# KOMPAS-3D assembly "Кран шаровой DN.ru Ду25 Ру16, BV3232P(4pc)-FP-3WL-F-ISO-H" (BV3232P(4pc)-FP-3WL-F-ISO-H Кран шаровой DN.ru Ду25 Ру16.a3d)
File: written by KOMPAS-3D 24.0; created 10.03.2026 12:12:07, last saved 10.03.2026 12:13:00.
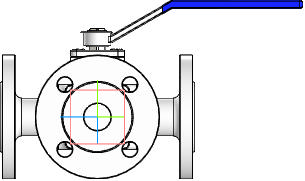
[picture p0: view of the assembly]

Document properties: Автор: R2D2; Полное имя файла: E:\Работа\Зайцев\BV3232P(4pc)-FP-3WL-F-ISO-H Кран шаровой DN.ru Ду15-100 Ру16\DN25\исходные материалы\BV3232P(4pc)-FP-3WL-F-ISO-H Кран шаровой DN.ru Ду25 Ру16.a3d

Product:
- Component [assembly]: Сборка1  | qty 1  | Масса: 6.687302; Автор: R2D2; source file: dn25_3d_step.a3d
- Part/product: Кран шаровой DN.ru Ду25 Ру16  | designation BV3232P(4pc)-FP-3WL-F-ISO-H
    Масса: 5.6
    Раздел спецификации: Прочие изделия
    Примечание: D160-36357

Referenced files in E:\Работа\Зайцев\BV3232P(4pc)-FP-3WL-F-ISO-H Кран шаровой DN.ru Ду15-100 Ру16\DN25\исходные материалы\: dn25_3d_step.a3d
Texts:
  BV3232P(4pc)-FP-3WL-F-ISO-H
  Сборка1 Сборка1
  Ось Z.Начало координат
  Ось Y.Начало координат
